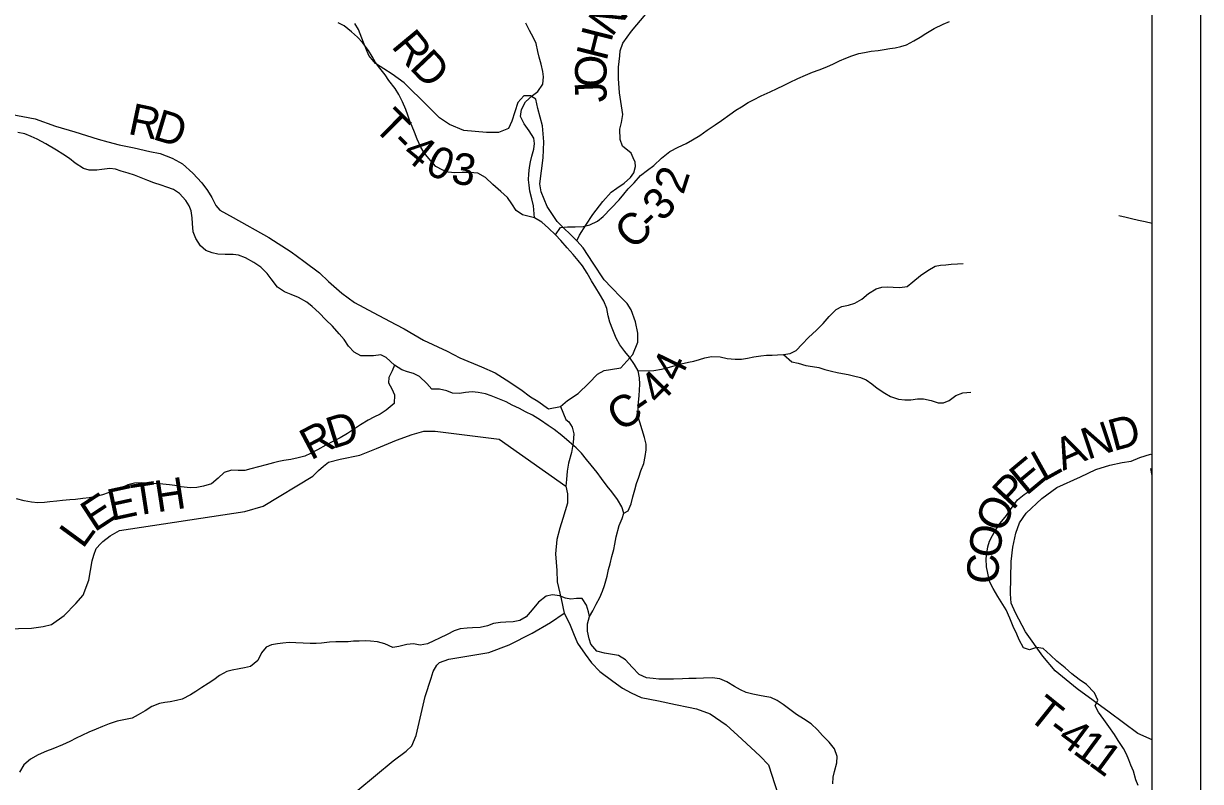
# Model space of a CAD drawing. Extents: x 0 to 34, y 0 to 22.
# Drawn here: x 6.965 to 9.087, y 15.393 to 16.76 of the extents above; entities that cross this region are included whole.
import ezdxf

# ---------------------------------------------------------------- set-up
doc = ezdxf.new("R2010")
doc.units = 0
for name, color, linetype in [('Default', 7, 'Continuous'), ('GM_X_County_Road', 7, 'Continuous'), ('GM_X_County_Road_Text', 7, 'Continuous'), ('GM_X_Major_River', 7, 'Continuous'), ('GM_X_Minor_River', 7, 'Continuous'), ('GM_X_Township_Road', 7, 'Continuous'), ('GM_X_Township_Road_Text', 7, 'Continuous'), ('SH_Cut_Line', 7, 'Continuous')]:
    doc.layers.add(name, color=color, linetype=linetype)

msp = doc.modelspace()

# ---------------------------------------------------------------- linework, layer by layer
at = {"layer": 'Default'}
msp.add_lwpolyline([(9.087, 13.8822), (2.1062, 13.8822), (2.1062, 20.9054), (9.087, 20.9054)], close=True, dxfattribs=at)
msp.add_lwpolyline([(4.485, 14), (9, 14), (9, 18.8941)], dxfattribs=at)
at = {"layer": 'GM_X_County_Road'}
for points in [[(7.9622, 16.3682), (7.9674, 16.3786), (7.9785, 16.3964), (7.9911, 16.4158), (8.009, 16.4392), (8.0246, 16.4559), (8.0345, 16.4631), (8.0478, 16.4722), (8.0592, 16.4824), (8.0653, 16.4911), (8.0684, 16.5025), (8.0673, 16.5101), (8.0642, 16.5177), (8.0601, 16.5264), (8.0446, 16.5393), (8.0404, 16.5511), (8.0401, 16.5697), (8.0432, 16.5815), (8.0451, 16.5963), (8.0396, 16.6354), (8.0374, 16.6612), (8.0374, 16.6817), (8.0398, 16.7018), (8.0406, 16.7109), (8.0452, 16.725), (8.0612, 16.7466), (8.0867, 16.7772)], [(6.9409, 16.597), (6.9856, 16.5881), (7.022, 16.5751), (7.0569, 16.5647), (7.099, 16.5517), (7.1168, 16.5471), (7.1373, 16.5413), (7.1642, 16.5359), (7.1926, 16.5294), (7.2109, 16.5259), (7.2328, 16.5175), (7.2461, 16.5103), (7.2514, 16.5072), (7.2699, 16.4904), (7.2862, 16.4729), (7.2964, 16.4589), (7.3039, 16.4463), (7.3115, 16.4322), (7.3187, 16.4239), (7.3429, 16.4101), (7.4069, 16.3743), (7.4471, 16.3487), (7.4702, 16.3319), (7.4986, 16.3106), (7.5148, 16.295), (7.5387, 16.274), (7.5614, 16.2569), (7.5951, 16.2389), (7.636, 16.2176), (7.6508, 16.2095), (7.686, 16.1889), (7.7285, 16.1691), (7.7512, 16.1572), (7.7906, 16.1412), (7.8149, 16.1301), (7.8349, 16.1179), (7.8614, 16.1), (7.8788, 16.087), (7.8921, 16.079), (7.911, 16.0656), (7.9328, 16.0696), (7.9428, 16.0462), (7.9481, 16.042), (7.9542, 16.0321), (7.9572, 16.02), (7.9556, 16.0044), (7.9525, 15.9869), (7.9471, 15.9676), (7.9448, 15.9528), (7.9436, 15.938), (7.9425, 15.9259), (7.9458, 15.9122), (7.9454, 15.8955), (7.9373, 15.8678), (7.9316, 15.85), (7.9266, 15.8295), (7.9239, 15.8037), (7.9264, 15.7737), (7.9267, 15.7536), (7.9342, 15.7228), (7.9395, 15.697), (7.9489, 15.678), (7.9564, 15.6605), (7.9636, 15.6426), (7.9775, 15.6232), (7.9889, 15.6076), (8.004, 15.5916), (8.0275, 15.5745), (8.0449, 15.5619), (8.0601, 15.5531), (8.0782, 15.5447), (8.1097, 15.5386), (8.1401, 15.532), (8.1639, 15.5274), (8.178, 15.5243), (8.203, 15.5151), (8.2314, 15.4953), (8.2601, 15.4698), (8.2931, 15.4389), (8.3082, 15.4233), (8.3311, 15.3523)], [(7.9328, 16.0696), (7.9454, 16.0804), (7.9646, 16.093), (7.9843, 16.1116), (7.9999, 16.1278), (8.0119, 16.1344), (8.0233, 16.1362), (8.0419, 16.1392), (8.0635, 16.1632), (8.0725, 16.1853), (8.0725, 16.2021), (8.0683, 16.2225), (8.0605, 16.2441), (8.0533, 16.2555), (8.0425, 16.2663), (8.0251, 16.2843), (8.0119, 16.298), (7.9921, 16.328), (7.9736, 16.3556), (7.9622, 16.3682)]]:
    msp.add_lwpolyline(points, dxfattribs=at)
at = {"layer": 'GM_X_Major_River'}
for points in [[(7.0356, 16.5245), (7.0242, 16.5318), (7.0046, 16.5434), (6.9894, 16.5514), (6.9781, 16.5565), (6.9671, 16.5611), (6.9542, 16.5635)], [(8.0223, 15.7856), (8.0258, 15.7993), (8.0289, 15.8118), (8.0309, 15.8216), (8.0333, 15.8345), (8.0388, 15.855), (8.0442, 15.8675), (8.0473, 15.877), (8.0436, 15.8888), (8.0357, 15.9017), (8.0256, 15.9158), (8.0169, 15.9258), (8.0068, 15.9399), (7.9989, 15.9506), (7.9883, 15.964), (7.9797, 15.9739), (7.971, 15.9857), (7.9612, 15.9953), (7.9484, 16.0056), (7.9356, 16.0171), (7.9216, 16.0282), (7.9106, 16.0355), (7.897, 16.0451), (7.8823, 16.054), (7.8698, 16.0601), (7.8588, 16.0659), (7.846, 16.0721), (7.835, 16.0779), (7.8202, 16.084), (7.8078, 16.0891), (7.7975, 16.0926), (7.7846, 16.0949), (7.7736, 16.0961), (7.7618, 16.0951), (7.7508, 16.0929), (7.7383, 16.0937), (7.7277, 16.0976), (7.7148, 16.1008), (7.7011, 16.1008), (7.6917, 16.1112), (7.6785, 16.1238), (7.6679, 16.1292), (7.6573, 16.1319), (7.6471, 16.1354), (7.6338, 16.1442), (7.6188, 16.158), (7.6089, 16.1627), (7.5956, 16.1612), (7.5823, 16.1609), (7.5728, 16.161), (7.5607, 16.1676), (7.5509, 16.1786), (7.5427, 16.1905), (7.5336, 16.2008), (7.522, 16.2142), (7.5099, 16.2256), (7.4975, 16.2386), (7.4854, 16.2501), (7.4756, 16.2578), (7.4605, 16.2659), (7.4472, 16.2717), (7.4351, 16.2763), (7.4226, 16.2848), (7.411, 16.2997), (7.4038, 16.3096), (7.3925, 16.3211), (7.3801, 16.3291), (7.3649, 16.3376), (7.3524, 16.3422), (7.3426, 16.3434), (7.3281, 16.3439), (7.3148, 16.3444), (7.3046, 16.3468), (7.2936, 16.3506), (7.2838, 16.3594), (7.2752, 16.3724), (7.2703, 16.3846), (7.2693, 16.3994), (7.2686, 16.4097), (7.2668, 16.4222), (7.2635, 16.4317), (7.2575, 16.4413), (7.2458, 16.4539), (7.2352, 16.4608), (7.2231, 16.4651), (7.2129, 16.4686), (7.1996, 16.4728), (7.189, 16.4771), (7.1765, 16.4817), (7.1648, 16.4868), (7.153, 16.4903), (7.1409, 16.4941), (7.1303, 16.4973), (7.1204, 16.4988), (7.106, 16.497), (7.0965, 16.496), (7.0832, 16.4957), (7.073, 16.4988), (7.0579, 16.5084), (7.0477, 16.5165), (7.0356, 16.5245)], [(8.424, 15.3889), (8.4245, 15.4011), (8.4269, 15.4113), (8.4312, 15.4272), (8.4316, 15.4382), (8.4272, 15.4523), (8.4174, 15.4645), (8.4057, 15.4764), (8.3967, 15.4863), (8.385, 15.4974), (8.371, 15.5066), (8.3586, 15.5143), (8.3442, 15.5251), (8.3344, 15.5324), (8.3238, 15.5393), (8.3121, 15.5447), (8.3015, 15.5466), (8.292, 15.5482), (8.2798, 15.5506), (8.2677, 15.5541), (8.2575, 15.5587), (8.2465, 15.5645), (8.2329, 15.5733), (8.22, 15.5784), (8.2064, 15.58), (8.1908, 15.5797), (8.1775, 15.5791), (8.1646, 15.5788), (8.1532, 15.5785), (8.1365, 15.5778), (8.1103, 15.578), (8.1, 15.5789), (8.0879, 15.5801), (8.075, 15.5863), (8.0622, 15.5993), (8.0501, 15.6126), (8.0373, 15.6203), (8.0233, 15.6231), (8.0123, 15.6247), (7.9982, 15.6286), (7.9877, 15.6412), (7.9844, 15.6507), (7.9818, 15.6644), (7.9819, 15.6777), (7.9854, 15.6906), (7.9912, 15.7012), (7.9974, 15.7129), (8.0039, 15.7254), (8.0086, 15.7364), (8.0125, 15.747), (8.0171, 15.7636), (8.0195, 15.7754), (8.0223, 15.7856)]]:
    msp.add_lwpolyline(points, dxfattribs=at)
at = {"layer": 'GM_X_Minor_River'}
msp.add_line((9, 15.9449), (8.9975, 15.9576), dxfattribs=at)
for points in [[(8.0473, 15.877), (8.0552, 15.8813), (8.0601, 15.8943), (8.0634, 15.9064), (8.0667, 15.9194), (8.07, 15.9308), (8.0741, 15.9422), (8.0778, 15.9533), (8.083, 15.967), (8.0859, 15.9792), (8.0873, 15.9913), (8.0872, 16.0016), (8.0845, 16.0137), (8.0805, 16.0277), (8.0759, 16.0413), (8.0731, 16.0512), (8.0727, 16.061), (8.073, 16.0705), (8.0751, 16.0895), (8.0757, 16.099), (8.076, 16.1097), (8.0755, 16.1211), (8.0728, 16.1336), (8.0666, 16.1456), (8.0574, 16.1585), (8.0489, 16.169), (8.0401, 16.1807), (8.0335, 16.1928), (8.0273, 16.2079), (8.0219, 16.2215), (8.0191, 16.2333), (8.0164, 16.2461), (8.0113, 16.2598), (8.0032, 16.2726), (7.9967, 16.2835), (7.989, 16.2964), (7.9812, 16.31), (7.9724, 16.3232), (7.9647, 16.333), (7.9559, 16.3435), (7.9451, 16.3559), (7.9336, 16.3687), (7.9241, 16.3789), (7.9114, 16.3913), (7.8995, 16.4018), (7.8862, 16.4097), (7.874, 16.413), (7.8645, 16.4155), (7.853, 16.423), (7.845, 16.4351), (7.8376, 16.4464), (7.8254, 16.4573), (7.8108, 16.47), (7.7974, 16.4828), (7.7837, 16.4903), (7.7693, 16.4913), (7.7556, 16.4915), (7.7423, 16.491), (7.7305, 16.4921), (7.7206, 16.4958), (7.7084, 16.5025), (7.6954, 16.5168), (7.6869, 16.5269), (7.6808, 16.5371), (7.6746, 16.5515), (7.6699, 16.5644), (7.6652, 16.5746), (7.6614, 16.5844), (7.6575, 16.595), (7.654, 16.6052), (7.6478, 16.6188), (7.6412, 16.632), (7.6346, 16.643), (7.6235, 16.6577), (7.6166, 16.6679), (7.607, 16.6795), (7.5993, 16.6901), (7.5935, 16.701), (7.5866, 16.7116), (7.5758, 16.7259), (7.567, 16.7357), (7.5559, 16.7451), (7.5429, 16.756), (7.5322, 16.7612)], [(7.8862, 16.4097), (7.8841, 16.4313), (7.881, 16.4438), (7.8774, 16.4578), (7.8762, 16.4688), (7.875, 16.4786), (7.8756, 16.4889), (7.877, 16.5007), (7.8788, 16.5109), (7.8814, 16.5212), (7.8847, 16.5334), (7.8862, 16.544), (7.8849, 16.5535), (7.8765, 16.5667), (7.8676, 16.5795), (7.8607, 16.5924), (7.8625, 16.6053), (7.8699, 16.6187), (7.8824, 16.6306), (7.8922, 16.6379), (7.9012, 16.6509), (7.9022, 16.6638), (7.901, 16.6736), (7.8982, 16.6869), (7.8947, 16.6994), (7.8923, 16.71), (7.8888, 16.7244), (7.8845, 16.7342), (7.8772, 16.7474), (7.8706, 16.7607)], [(7.9241, 16.3789), (7.9327, 16.3926), (7.9456, 16.3935), (7.9592, 16.3933), (7.974, 16.3942), (7.9858, 16.3973), (7.9994, 16.4039), (8.01, 16.4124), (8.0246, 16.4273), (8.0386, 16.4422), (8.0472, 16.4522), (8.0551, 16.4618), (8.0656, 16.4729), (8.0773, 16.4859), (8.0901, 16.4959), (8.1011, 16.5044), (8.115, 16.5174), (8.1301, 16.5297), (8.1452, 16.5374), (8.1596, 16.544), (8.1709, 16.5502), (8.1841, 16.5583), (8.1977, 16.5679), (8.2117, 16.5772), (8.2234, 16.5856), (8.2385, 16.596), (8.2491, 16.6037), (8.2596, 16.6099), (8.2714, 16.6176), (8.2812, 16.6226), (8.2948, 16.63), (8.3111, 16.6373), (8.3235, 16.6428), (8.3349, 16.6482), (8.3459, 16.6536), (8.361, 16.661), (8.3746, 16.6668), (8.3875, 16.6723), (8.3996, 16.6765), (8.4132, 16.682), (8.4253, 16.6878), (8.4359, 16.6928), (8.4476, 16.6979), (8.4582, 16.7022), (8.4707, 16.7061), (8.481, 16.7081), (8.4931, 16.7101), (8.5056, 16.7117), (8.5166, 16.7134), (8.5268, 16.715), (8.5363, 16.7166), (8.5469, 16.7186), (8.5568, 16.7217), (8.5704, 16.7287), (8.5814, 16.7353), (8.5919, 16.7422), (8.607, 16.7511), (8.6229, 16.7592), (8.6343, 16.7639)], [(9, 16.3998), (8.9876, 16.4025), (8.9754, 16.405), (8.9628, 16.4079), (8.9533, 16.4101), (8.94, 16.4134)], [(8.0728, 16.1336), (8.1013, 16.1346), (8.1153, 16.1366), (8.1251, 16.139), (8.1399, 16.1433), (8.1505, 16.1465), (8.1638, 16.1496), (8.1733, 16.1516), (8.1835, 16.1544), (8.1933, 16.1571), (8.2055, 16.1599), (8.2207, 16.1593), (8.2336, 16.1564), (8.2477, 16.155), (8.2594, 16.1547), (8.2701, 16.1567), (8.2818, 16.1591), (8.2943, 16.1611), (8.3042, 16.162), (8.3148, 16.1621), (8.3243, 16.1626), (8.3349, 16.1634), (8.3471, 16.1654), (8.3577, 16.1708), (8.3686, 16.182), (8.3799, 16.1938), (8.3946, 16.2073), (8.4066, 16.2192), (8.4175, 16.2318), (8.4303, 16.2444), (8.4405, 16.2499), (8.4526, 16.2526), (8.464, 16.2558), (8.4761, 16.2631), (8.4882, 16.2735), (8.5025, 16.282), (8.5127, 16.2847), (8.523, 16.2852), (8.5329, 16.2849), (8.545, 16.2839), (8.5583, 16.2859), (8.5685, 16.2944), (8.5824, 16.3055), (8.5953, 16.3151), (8.6085, 16.3225), (8.618, 16.3245), (8.6278, 16.3249), (8.6377, 16.3262), (8.6491, 16.3267), (8.659, 16.3275)], [(8.3349, 16.1634), (8.3499, 16.1499), (8.3617, 16.1477), (8.3754, 16.1437), (8.3875, 16.1415), (8.3986, 16.1397), (8.4096, 16.1364), (8.4214, 16.1335), (8.4317, 16.1309), (8.4416, 16.1288), (8.4518, 16.127), (8.4614, 16.1248), (8.4739, 16.1219), (8.4842, 16.1178), (8.4945, 16.1107), (8.5041, 16.1024), (8.5178, 16.0934), (8.5281, 16.0875), (8.5426, 16.0827), (8.5536, 16.0813), (8.565, 16.0817), (8.5768, 16.0834), (8.5874, 16.0835), (8.6011, 16.0802), (8.6141, 16.0761), (8.6236, 16.0759), (8.6338, 16.0805), (8.6459, 16.0894), (8.6587, 16.094), (8.6731, 16.0957)], [(7.6338, 16.1442), (7.6292, 16.1338), (7.6232, 16.122), (7.6226, 16.1125), (7.6287, 16.1012), (7.6338, 16.0906), (7.6332, 16.0747), (7.6188, 16.0631), (7.6079, 16.0558), (7.5961, 16.0504), (7.5859, 16.045), (7.5723, 16.0365), (7.5614, 16.0295), (7.5486, 16.0211), (7.5353, 16.013), (7.5236, 16.0072), (7.51, 15.9998), (7.4949, 15.9917), (7.482, 15.9847), (7.4718, 15.9801), (7.4597, 15.9769), (7.4464, 15.9742), (7.4343, 15.9721), (7.4248, 15.9705), (7.4153, 15.9682), (7.4021, 15.9646), (7.3884, 15.9607), (7.3744, 15.9571), (7.3634, 15.9544), (7.3517, 15.9543), (7.3395, 15.9545), (7.3266, 15.9506), (7.3157, 15.9402), (7.3033, 15.9303), (7.2892, 15.9259), (7.2771, 15.9236), (7.265, 15.9231), (7.2486, 15.9248), (7.2372, 15.927), (7.2277, 15.9284), (7.2159, 15.9294), (7.2041, 15.9301), (7.1908, 15.9311), (7.1772, 15.9317), (7.1646, 15.9316), (7.1529, 15.9284), (7.1415, 15.923), (7.1283, 15.9187), (7.1173, 15.914), (7.1067, 15.9101), (7.0957, 15.907), (7.0828, 15.9046), (7.0715, 15.9034), (7.0586, 15.9021), (7.0483, 15.9012), (7.0347, 15.9), (7.0244, 15.8987), (7.0123, 15.8975), (7.0024, 15.8962), (6.9906, 15.8961), (6.9792, 15.8968), (6.9659, 15.8993), (6.9518, 15.903)], [(8.9744, 15.3864), (8.9705, 15.3966), (8.9662, 15.4118), (8.9616, 15.4227), (8.9581, 15.4326), (8.9534, 15.4428), (8.948, 15.453), (8.9388, 15.4673), (8.9318, 15.4783), (8.9218, 15.4926), (8.9126, 15.5054), (8.903, 15.5182), (8.8972, 15.5299), (8.9017, 15.5402), (8.8959, 15.5531), (8.8813, 15.5681), (8.8683, 15.5775), (8.8553, 15.5872), (8.8431, 15.5981), (8.8281, 15.6101), (8.8167, 15.6214), (8.8033, 15.6334), (8.7911, 15.6352), (8.779, 15.6309), (8.7676, 15.6346), (8.7598, 15.6489), (8.7559, 15.6588), (8.7494, 15.6728), (8.7435, 15.6879), (8.7366, 15.7026), (8.7304, 15.7128), (8.7219, 15.7268), (8.7134, 15.7415), (8.7065, 15.754), (8.7033, 15.7691), (8.7013, 15.7805), (8.7008, 15.7949), (8.7015, 15.8052), (8.7033, 15.8166), (8.7066, 15.8269), (8.7119, 15.8368), (8.7175, 15.8463), (8.7261, 15.8589), (8.7374, 15.8731), (8.7464, 15.8865), (8.7569, 15.901), (8.7689, 15.911), (8.7818, 15.9195), (8.7965, 15.9295)], [(7.9854, 15.6906), (7.9835, 15.6992), (7.98, 15.7113), (7.9719, 15.7233), (7.9617, 15.7232), (7.9518, 15.722), (7.9419, 15.7242), (7.9313, 15.7279), (7.9183, 15.7297), (7.907, 15.7273), (7.893, 15.7165), (7.8817, 15.7027), (7.8712, 15.6905), (7.8595, 15.6835), (7.8477, 15.6811), (7.8344, 15.6806), (7.825, 15.6802), (7.8124, 15.6785), (7.8011, 15.6742), (7.7878, 15.6711), (7.7742, 15.6702), (7.7647, 15.6701), (7.7518, 15.6684), (7.7412, 15.6649), (7.7287, 15.6584), (7.7147, 15.6518), (7.7045, 15.6471), (7.6931, 15.6417), (7.6799, 15.6389), (7.6677, 15.6414), (7.6556, 15.6402), (7.6412, 15.6366), (7.6305, 15.635), (7.616, 15.6417), (7.6031, 15.645), (7.5902, 15.6464), (7.5807, 15.6471), (7.5697, 15.6466), (7.5598, 15.6461), (7.5499, 15.6452), (7.5275, 15.645), (7.5161, 15.6445), (7.5017, 15.6429), (7.4922, 15.6424), (7.4816, 15.6423), (7.4687, 15.6426), (7.4558, 15.6432), (7.4436, 15.6438), (7.4322, 15.643), (7.4224, 15.6417), (7.4117, 15.6397), (7.4019, 15.6355), (7.394, 15.6255), (7.3869, 15.6118), (7.3741, 15.6007), (7.3631, 15.5983), (7.3533, 15.5963), (7.3408, 15.5943), (7.3313, 15.5915), (7.3181, 15.5846), (7.3075, 15.5765), (7.2973, 15.5703), (7.2863, 15.5626), (7.2754, 15.5557), (7.2656, 15.5495), (7.2508, 15.5418), (7.2402, 15.5394), (7.2288, 15.537), (7.2194, 15.5358), (7.2095, 15.5338), (7.1959, 15.5287), (7.1842, 15.521), (7.1713, 15.5137), (7.1607, 15.5075), (7.1456, 15.5043), (7.1334, 15.5019), (7.1191, 15.4972), (7.1069, 15.4925), (7.0956, 15.4875), (7.0824, 15.4821), (7.0695, 15.4762), (7.0597, 15.4716), (7.0479, 15.4654), (7.0347, 15.4592), (7.0177, 15.4522), (7.0063, 15.4483), (6.9908, 15.4417), (6.9772, 15.4336), (6.9651, 15.4232), (6.9573, 15.4102)]]:
    msp.add_lwpolyline(points, dxfattribs=at)
at = {"layer": 'GM_X_Township_Road'}
for points in [[(7.9622, 16.3682), (7.9268, 16.403), (7.9088, 16.4305), (7.898, 16.4569), (7.8956, 16.4713), (7.9016, 16.5181), (7.9028, 16.5468), (7.9004, 16.5756), (7.892, 16.6068), (7.8884, 16.6236), (7.8788, 16.6296), (7.8668, 16.6296), (7.8561, 16.6176), (7.8453, 16.584), (7.8393, 16.5708), (7.8213, 16.5636), (7.7997, 16.5636), (7.7589, 16.5672), (7.7326, 16.578), (7.7146, 16.59), (7.693, 16.6116), (7.651, 16.6535), (7.6294, 16.6691), (7.5995, 16.6883), (7.5875, 16.7027), (7.5779, 16.7261), (7.5689, 16.7495), (7.5623, 16.7603)], [(7.104, 15.8227), (7.1073, 15.8263), (7.1206, 15.8361), (7.1374, 15.8459), (7.3636, 15.8802), (7.3967, 15.8899), (7.4864, 15.9439), (7.4963, 15.9542), (7.5058, 15.9621), (7.5146, 15.9689), (7.5354, 15.9745), (7.5708, 15.982), (7.6012, 15.9941), (7.6373, 16.0088), (7.6657, 16.0189), (7.6866, 16.0249), (7.7071, 16.0253), (7.8221, 16.0105), (7.9425, 15.9259)], [(9, 15.4684), (8.974, 15.4798), (8.9221, 15.5183), (8.8649, 15.5606), (8.8252, 15.593), (8.8025, 15.6192), (8.7715, 15.6634), (8.7534, 15.6976), (8.7459, 15.7151), (8.7444, 15.7318), (8.7454, 15.7898), (8.7485, 15.8157), (8.7539, 15.8411), (8.7604, 15.8596), (8.773, 15.8774), (8.8011, 15.9036), (8.8281, 15.9236), (8.8707, 15.9428), (8.8984, 15.9557), (8.9235, 15.9636), (8.9459, 15.9688), (8.9619, 15.971), (8.9774, 15.9778), (8.9968, 15.9838), (9, 15.9826)], [(6.4651, 15.6006), (6.4911, 15.5981), (6.6519, 15.5938), (6.7078, 15.5906), (6.7298, 15.5921), (6.7484, 15.5989), (6.815, 15.6423), (6.8476, 15.665), (6.8575, 15.6684), (6.9554, 15.6692), (6.9789, 15.6699), (7.0002, 15.6729), (7.015, 15.6766), (7.0378, 15.6929), (7.0592, 15.7141), (7.0721, 15.7292), (7.0821, 15.7561), (7.0882, 15.7914), (7.0913, 15.8013), (7.0955, 15.8134), (7.104, 15.8227)], [(6.9301, 15.213), (7.0006, 15.2113), (7.0955, 15.2144), (7.2781, 15.2272), (7.3513, 15.2322), (7.3771, 15.2329), (7.3958, 15.2386), (7.5354, 15.3513), (7.6309, 15.4303), (7.6545, 15.4481), (7.6647, 15.4575), (7.6724, 15.4765), (7.6889, 15.5467), (7.6996, 15.5797), (7.7035, 15.5918), (7.71, 15.6032), (7.7149, 15.6081), (7.7313, 15.6137), (7.8034, 15.626), (7.8406, 15.64), (7.8817, 15.6607), (7.9147, 15.68), (7.9395, 15.697)]]:
    msp.add_lwpolyline(points, dxfattribs=at)
at = {"layer": 'SH_Cut_Line'}
msp.add_lwpolyline([(2.2, 19.4329), (2.2, 14), (9, 14), (9, 18.8941), (8.8762, 18.9027), (8.0305, 18.9725), (6.8442, 19.0679), (6.226, 19.1161), (5.8337, 19.1499), (5.3224, 19.1939), (5.1554, 19.2083), (4.831, 19.2363), (4.7641, 19.2419), (3.1893, 19.3592), (2.7961, 19.3885)], close=True, dxfattribs=at)

# ---------------------------------------------------------------- texts
at = {"layer": 'GM_X_County_Road_Text'}
for s, rotation, p in [('N', 53.8208, (8.0256, 16.7343)), ('H', 75.7597, (8.0158, 16.691)), ('O', 89.3552, (8.0157, 16.6445)), ('J', 92.2546, (8.0167, 16.6187)), ('R', 348.1282, (7.1511, 16.5615)), ('D', 343.2425, (7.1955, 16.5522)), ('2', 72.1892, (8.1543, 16.4501)), ('3', 47.0333, (8.1168, 16.4011)), ('C', 43.8933, (8.0641, 16.35)), ('-', 44.3329, (8.0981, 16.3827)), ('4', 63.9992, (8.1462, 16.1112)), ('4', 45.4771, (8.1101, 16.07)), ('C', 31.7001, (8.0397, 16.0228)), ('-', 34.9449, (8.0823, 16.0493))]:
    msp.add_text(s, height=0.0568, rotation=rotation, dxfattribs=at).set_placement(p)
at = {"layer": 'GM_X_Township_Road_Text'}
for s, rotation, p in [('R', 309.6632, (7.6264, 16.7187)), ('D', 313.607, (7.659, 16.6796)), ('T', 315.1667, (7.5935, 16.5723)), ('-', 315.902, (7.6242, 16.5418)), ('4', 320.7291, (7.6449, 16.5221)), ('0', 336.4768, (7.6865, 16.4911)), ('3', 351.2992, (7.7339, 16.4727)), ('D', 17.4477, (7.5215, 15.9926)), ('D', 15.0497, (8.9302, 15.9888)), ('R', 27.8236, (7.4827, 15.9719)), ('N', 18.4545, (8.8836, 15.9732)), ('A', 24.1175, (8.8394, 15.9533)), ('L', 29.1016, (8.8034, 15.9332)), ('E', 39.7441, (8.773, 15.9076)), ('H', 8.6814, (7.2057, 15.8786)), ('P', 47.0835, (8.7483, 15.8809)), ('E', 12.2294, (7.1231, 15.8632)), ('T', 8.7726, (7.1637, 15.8721)), ('E', 33.192, (7.0925, 15.8421)), ('O', 65.7065, (8.7304, 15.8393)), ('L', 53.857, (7.0714, 15.8115)), ('O', 80.9868, (8.7237, 15.7938)), ('C', 88.2863, (8.7225, 15.749)), ('T', 321.3221, (8.773, 15.5085)), ('-', 322.9587, (8.8076, 15.4808)), ('4', 323.3713, (8.8265, 15.4665)), ('1', 323.6451, (8.8549, 15.4455)), ('1', 323.7011, (8.8831, 15.4247))]:
    msp.add_text(s, height=0.0568, rotation=rotation, dxfattribs=at).set_placement(p)

doc.saveas('drawing.dxf')
